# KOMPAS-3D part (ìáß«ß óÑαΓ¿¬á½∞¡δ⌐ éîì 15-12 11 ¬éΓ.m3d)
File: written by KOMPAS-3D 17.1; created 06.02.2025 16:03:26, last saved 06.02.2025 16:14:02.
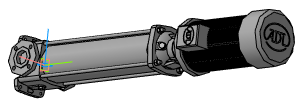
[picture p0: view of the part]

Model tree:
1. Операция без истории:1  (labels: Насос вертикальный ВМН 15-12 11 кВт)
